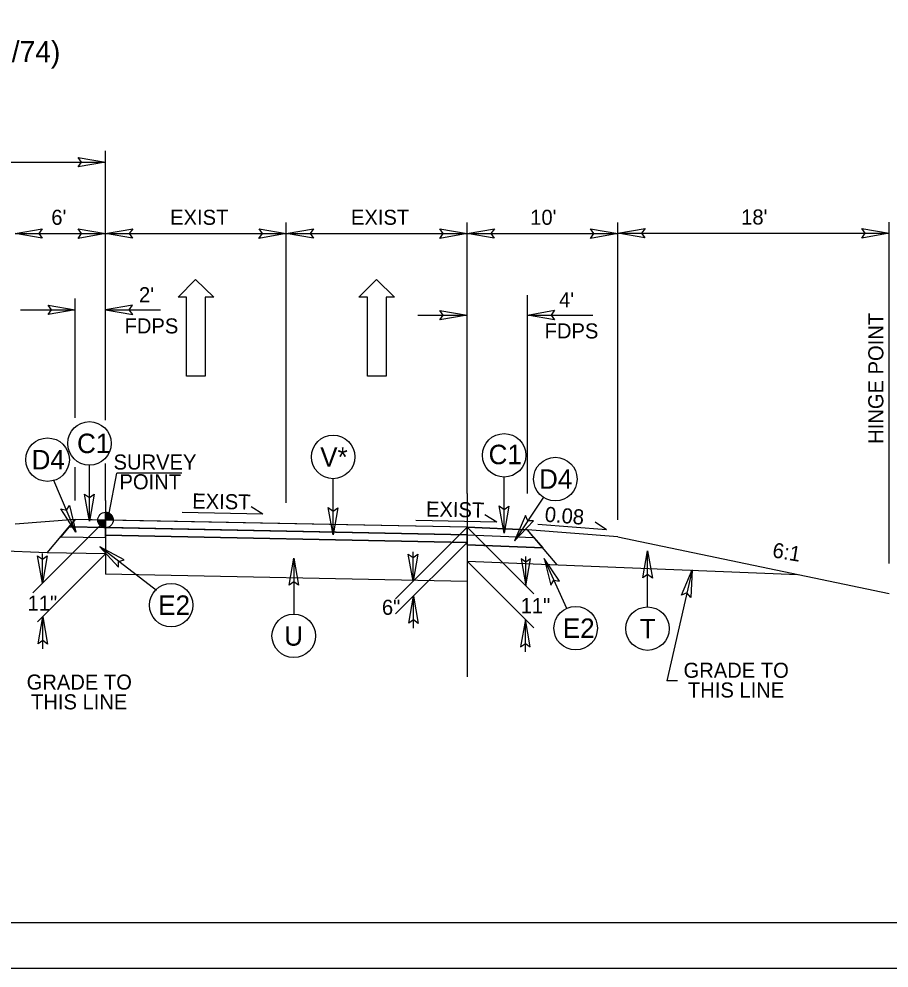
# Model space of a CAD drawing. Extents: x 18938 to 19565, y 6931 to 7973.
# Drawn here: x 19289 to 19346.7, y 7224.9 to 7287.9 of the extents above; entities that cross this region are included whole.
import ezdxf

# ---------------------------------------------------------------- set-up
doc = ezdxf.new("R2010")
doc.units = 0
for name, color, linetype in [('Old_Level_1', 7, 'Continuous'), ('Old_Level_11', 7, 'Continuous'), ('Old_Level_2', 7, 'Continuous'), ('Old_Level_3', 7, 'Continuous'), ('Prop Dimension', 7, 'Continuous'), ('Prop Pavement Schedule Description CELL', 7, 'Continuous'), ('Prop Shade Light', 7, 'Continuous'), ('Prop Terminator CELL', 7, 'Continuous'), ('Sheet Block Title CELL', 7, 'Continuous'), ('Sheet Data Field CELL', 7, 'Continuous'), ('Sheet Plot Border Inside CELL', 7, 'Continuous'), ('Sheet Plot Border Outside CELL', 7, 'Continuous'), ('Sheet Typical CELL', 7, 'Continuous'), ('Typical Bridge Rail Two Bar CELL', 7, 'Continuous'), ('Typical Detail Wedge1 CELL', 7, 'Continuous'), ('Typical Detail Wedge3 CELL', 7, 'Continuous'), ('Typical Hinge Slope Arterial CELL', 7, 'Continuous'), ('Typical ID Circle CELL', 7, 'Continuous'), ('Typical Pavement Slope Information CELL', 7, 'Continuous'), ('Typical Shoulder Slope Information CELL', 7, 'Continuous'), ('Typical Terminator CELL', 7, 'Continuous'), ('Typical Text Grade Point CELL', 7, 'Continuous'), ('Typical Text ID Circle CELL', 7, 'Continuous'), ('Typical Text Label CELL', 7, 'Continuous')]:
    doc.layers.add(name, color=color, linetype=linetype)

msp = doc.modelspace()

# ---------------------------------------------------------------- linework, layer by layer
at = {"layer": 'Old_Level_1'}
for p, q in [((19290.827, 7252.435), (19292.697, 7254.648)), ((19318.697, 7254.128), (19292.697, 7254.648)), ((19318.697, 7254.128), (19322.697, 7253.968)), ((19324.666, 7251.639), (19322.697, 7253.968)), ((19318.697, 7253.128), (19294.697, 7253.608)), ((19318.697, 7253.628), (19323.135, 7253.45)), ((19294.697, 7252.358), (19290.827, 7252.435)), ((19318.697, 7252.961), (19323.718, 7252.76)), ((19318.697, 7252.961), (19318.697, 7252.961)), ((19318.697, 7251.878), (19340.637, 7251))]:
    msp.add_line(p, q, dxfattribs=at)
at = {"layer": 'Old_Level_3'}
for p, q in [((19294.697, 7261.245), (19294.697, 7279.12)), ((19258.697, 7278.369), (19294.697, 7278.369)), ((19328.697, 7254.619), (19328.697, 7274.356)), ((19346.697, 7251.725), (19346.697, 7274.376)), ((19288.697, 7273.621), (19294.697, 7273.621)), ((19294.697, 7273.621), (19306.697, 7273.621)), ((19306.697, 7273.621), (19318.697, 7273.621)), ((19318.697, 7273.621), (19328.697, 7273.621)), ((19328.697, 7273.641), (19346.697, 7273.641)), ((19292.697, 7261.402), (19292.697, 7269.304)), ((19289.055, 7268.568), (19292.697, 7268.568)), ((19294.697, 7268.568), (19298.34, 7268.568)), ((19315.422, 7268.209), (19318.697, 7268.209)), ((19322.697, 7268.209), (19327.044, 7268.209)), ((19292.697, 7255.908), (19292.697, 7258.107)), ((19294.697, 7255.908), (19294.697, 7258.368)), ((19294.698, 7254.608), (19289.874, 7249.784)), ((19318.697, 7254.128), (19313.951, 7249.381)), ((19318.697, 7254.128), (19323.116, 7249.709)), ((19318.697, 7253.128), (19313.951, 7248.381)), ((19315.111, 7250.542), (19315.111, 7252.497)), ((19294.698, 7252.358), (19290.182, 7247.842)), ((19290.515, 7250.425), (19290.515, 7252.381)), ((19318.697, 7251.878), (19323.116, 7247.459)), ((19322.591, 7250.234), (19322.591, 7252.19)), ((19333.624, 7251.31), (19331.962, 7243.94)), ((19315.133, 7247.427), (19315.133, 7249.556)), ((19290.537, 7246.061), (19290.537, 7248.19)), ((19322.569, 7245.869), (19322.569, 7247.999)), ((19332.669, 7243.94), (19331.962, 7243.94))]:
    msp.add_line(p, q, dxfattribs=at)
at = {"layer": 'Prop Dimension'}
msp.add_lwpolyline([(19155.167, 7224.873), (19382.434, 7224.873), (19382.434, 7371.306), (19155.167, 7371.306)], close=True, dxfattribs=at)
at = {"layer": 'Prop Pavement Schedule Description CELL'}
for p, q in [((19292.697, 7254.648), (19288.697, 7254.328)), ((19328.697, 7253.488), (19322.697, 7253.968)), ((19328.697, 7253.488), (19346.698, 7249.738)), ((19290.827, 7252.435), (19280.455, 7252.869))]:
    msp.add_line(p, q, dxfattribs=at)
at = {"layer": 'Sheet Block Title CELL'}
for p, q in [((19292.282, 7254.156), (19291.728, 7253.501)), ((19294.697, 7254.108), (19292.282, 7254.156)), ((19294.697, 7253.441), (19294.697, 7254.108)), ((19318.697, 7253.628), (19294.799, 7254.106)), ((19291.728, 7253.501), (19294.697, 7253.441)), ((19318.697, 7253.628), (19323.135, 7253.45)), ((19318.697, 7252.961), (19318.697, 7253.628)), ((19323.135, 7253.45), (19323.718, 7252.76)), ((19323.718, 7252.76), (19318.697, 7252.961)), ((19318.697, 7252.961), (19318.697, 7252.961)), ((19318.697, 7252.961), (19318.697, 7252.961))]:
    msp.add_line(p, q, dxfattribs=at)
at = {"layer": 'Sheet Data Field CELL'}
for points in [[(19292.897, 7278.679), (19294.697, 7278.369), (19292.887, 7278.049), (19293.117, 7278.369)], [(19290.497, 7273.311), (19288.697, 7273.621), (19290.507, 7273.941), (19290.277, 7273.621)], [(19292.897, 7273.931), (19294.697, 7273.621), (19292.887, 7273.301), (19293.117, 7273.621)], [(19296.497, 7273.311), (19294.697, 7273.621), (19296.507, 7273.941), (19296.277, 7273.621)], [(19304.897, 7273.931), (19306.697, 7273.621), (19304.887, 7273.301), (19305.117, 7273.621)], [(19308.497, 7273.311), (19306.697, 7273.621), (19308.507, 7273.941), (19308.277, 7273.621)], [(19316.897, 7273.931), (19318.697, 7273.621), (19316.887, 7273.301), (19317.117, 7273.621)], [(19320.497, 7273.311), (19318.697, 7273.621), (19320.507, 7273.941), (19320.277, 7273.621)], [(19326.897, 7273.931), (19328.697, 7273.621), (19326.887, 7273.301), (19327.117, 7273.621)], [(19330.497, 7273.331), (19328.697, 7273.641), (19330.507, 7273.961), (19330.277, 7273.641)], [(19344.897, 7273.951), (19346.697, 7273.641), (19344.887, 7273.321), (19345.117, 7273.641)], [(19290.897, 7268.878), (19292.697, 7268.568), (19290.887, 7268.248), (19291.117, 7268.568)], [(19296.497, 7268.878), (19294.697, 7268.568), (19296.507, 7268.248), (19296.277, 7268.568)], [(19316.897, 7268.519), (19318.697, 7268.209), (19316.887, 7267.889), (19317.117, 7268.209)], [(19324.497, 7267.899), (19322.697, 7268.209), (19324.507, 7268.529), (19324.277, 7268.209)], [(19293.946, 7256.326), (19293.636, 7254.526), (19293.316, 7256.336), (19293.636, 7256.106)], [(19292.315, 7255.578), (19292.727, 7253.798), (19291.73, 7255.343), (19292.114, 7255.255)], [(19310.117, 7255.425), (19309.807, 7253.625), (19309.487, 7255.435), (19309.807, 7255.205)], [(19321.466, 7255.535), (19321.156, 7253.735), (19320.836, 7255.545), (19321.156, 7255.315)], [(19322.582, 7254.901), (19321.85, 7253.228), (19323.113, 7254.562), (19322.72, 7254.547)], [(19295.931, 7251.973), (19294.317, 7252.829), (19295.553, 7251.469), (19295.567, 7251.863)], [(19330.361, 7250.77), (19330.671, 7252.57), (19330.991, 7250.76), (19330.671, 7250.99)], [(19290.825, 7252.225), (19290.515, 7250.425), (19290.195, 7252.235), (19290.515, 7252.005)], [(19306.881, 7250.286), (19307.191, 7252.086), (19307.511, 7250.276), (19307.191, 7250.506)], [(19315.421, 7252.342), (19315.111, 7250.542), (19314.791, 7252.352), (19315.111, 7252.122)], [(19322.281, 7252.034), (19322.591, 7250.234), (19322.911, 7252.044), (19322.591, 7251.814)], [(19324.834, 7250.553), (19323.811, 7252.066), (19324.263, 7250.285), (19324.46, 7250.626)], [(19332.925, 7249.623), (19333.624, 7251.31), (19333.538, 7249.474), (19333.276, 7249.769)], [(19314.823, 7247.756), (19315.133, 7249.556), (19315.453, 7247.746), (19315.133, 7247.976)], [(19290.227, 7246.39), (19290.537, 7248.19), (19290.857, 7246.38), (19290.537, 7246.61)], [(19322.879, 7246.199), (19322.569, 7247.999), (19322.249, 7246.189), (19322.569, 7246.419)]]:
    msp.add_lwpolyline(points, close=True, dxfattribs=at)
at = {"layer": 'Sheet Typical CELL'}
for p, q in [((19306.697, 7255.743), (19306.697, 7274.356)), ((19318.697, 7256.372), (19318.697, 7274.356)), ((19322.697, 7256.372), (19322.697, 7269.543))]:
    msp.add_line(p, q, dxfattribs=at)
at = {"layer": 'Typical Bridge Rail Two Bar CELL'}
for p, q in [((19318.697, 7256.372), (19318.697, 7244.193)), ((19294.697, 7255.908), (19294.697, 7251.019))]:
    msp.add_line(p, q, dxfattribs=at)
at = {"layer": 'Typical Detail Wedge1 CELL'}
for p, q in [((19294.698, 7254.608), (19294.698, 7255.12)), ((19294.186, 7254.608), (19294.698, 7254.608)), ((19294.697, 7254.096), (19294.698, 7254.608)), ((19294.698, 7254.608), (19294.697, 7254.096)), ((19295.21, 7254.608), (19294.698, 7254.608))]:
    msp.add_line(p, q, dxfattribs=at)
for points in [[(19294.703, 7255.12), (19294.703, 7255.12), (19294.703, 7254.608)], [(19294.713, 7255.119), (19294.713, 7254.608)], [(19294.723, 7255.119), (19294.723, 7254.608)], [(19294.734, 7255.119), (19294.733, 7254.608)], [(19294.744, 7255.117), (19294.744, 7254.608)], [(19294.754, 7255.117), (19294.754, 7254.608)], [(19294.764, 7255.116), (19294.764, 7254.608)], [(19294.774, 7255.114), (19294.774, 7254.608)], [(19294.785, 7255.112), (19294.784, 7254.608)], [(19294.795, 7255.11), (19294.795, 7254.608)], [(19294.805, 7255.108), (19294.805, 7254.608)], [(19294.815, 7255.106), (19294.815, 7254.608)], [(19294.826, 7255.104), (19294.826, 7254.608)], [(19294.836, 7255.101), (19294.836, 7254.608)], [(19294.846, 7255.098), (19294.846, 7254.608)], [(19294.857, 7255.095), (19294.857, 7254.608)], [(19294.867, 7255.091), (19294.867, 7254.608)], [(19294.877, 7255.087), (19294.877, 7254.608)], [(19294.887, 7255.084), (19294.887, 7254.608)], [(19294.898, 7255.079), (19294.897, 7254.608)], [(19294.908, 7255.075), (19294.908, 7254.608)], [(19294.918, 7255.07), (19294.918, 7254.608)], [(19294.928, 7255.065), (19294.928, 7254.608)], [(19294.938, 7255.06), (19294.938, 7254.608)], [(19294.949, 7255.054), (19294.948, 7254.608)], [(19294.959, 7255.048), (19294.959, 7254.608)], [(19294.969, 7255.042), (19294.969, 7254.608)], [(19294.979, 7255.035), (19294.979, 7254.608)], [(19294.989, 7255.029), (19294.989, 7254.608)], [(19295, 7255.021), (19295, 7254.608)], [(19295.01, 7255.013), (19295.01, 7254.608)], [(19295.02, 7255.005), (19295.02, 7254.608)], [(19295.03, 7254.997), (19295.03, 7254.608)], [(19295.041, 7254.988), (19295.041, 7254.608)], [(19295.051, 7254.978), (19295.051, 7254.608)], [(19295.061, 7254.968), (19295.061, 7254.608)], [(19295.072, 7254.958), (19295.072, 7254.608)], [(19295.082, 7254.946), (19295.082, 7254.608)], [(19294.189, 7254.608), (19294.189, 7254.552)], [(19294.199, 7254.608), (19294.199, 7254.492)], [(19294.209, 7254.608), (19294.209, 7254.454)], [(19294.22, 7254.608), (19294.22, 7254.425)], [(19294.23, 7254.608), (19294.23, 7254.4)], [(19294.24, 7254.608), (19294.24, 7254.378)], [(19294.25, 7254.608), (19294.25, 7254.359)], [(19294.26, 7254.608), (19294.26, 7254.342)], [(19294.271, 7254.608), (19294.271, 7254.326)], [(19294.281, 7254.608), (19294.281, 7254.31)], [(19294.291, 7254.608), (19294.291, 7254.297)], [(19294.301, 7254.608), (19294.301, 7254.284)], [(19294.311, 7254.608), (19294.311, 7254.272)], [(19294.322, 7254.608), (19294.322, 7254.26)], [(19294.332, 7254.608), (19294.332, 7254.249)], [(19294.342, 7254.608), (19294.342, 7254.239)], [(19294.353, 7254.608), (19294.353, 7254.23)], [(19294.363, 7254.608), (19294.363, 7254.221)], [(19294.373, 7254.608), (19294.373, 7254.212)], [(19294.383, 7254.608), (19294.383, 7254.204)], [(19294.394, 7254.608), (19294.394, 7254.196)], [(19294.404, 7254.608), (19294.404, 7254.189)], [(19294.414, 7254.608), (19294.414, 7254.181)], [(19294.424, 7254.608), (19294.424, 7254.175)], [(19294.435, 7254.608), (19294.434, 7254.168)], [(19294.445, 7254.608), (19294.445, 7254.162)], [(19294.455, 7254.608), (19294.455, 7254.157)], [(19294.465, 7254.608), (19294.465, 7254.152)], [(19294.475, 7254.608), (19294.475, 7254.146)], [(19294.486, 7254.608), (19294.485, 7254.142)], [(19294.496, 7254.608), (19294.496, 7254.137)], [(19294.506, 7254.608), (19294.506, 7254.133)], [(19294.516, 7254.608), (19294.516, 7254.129)], [(19294.527, 7254.608), (19294.527, 7254.125)], [(19294.537, 7254.608), (19294.537, 7254.121)], [(19294.547, 7254.608), (19294.547, 7254.118)], [(19294.557, 7254.608), (19294.557, 7254.115)], [(19294.568, 7254.608), (19294.568, 7254.112)], [(19294.578, 7254.608), (19294.578, 7254.11)], [(19294.588, 7254.608), (19294.588, 7254.108)], [(19294.599, 7254.608), (19294.598, 7254.105)], [(19294.609, 7254.608), (19294.609, 7254.104)], [(19294.619, 7254.608), (19294.619, 7254.102)], [(19294.629, 7254.608), (19294.629, 7254.1)], [(19294.639, 7254.608), (19294.639, 7254.099)], [(19294.65, 7254.608), (19294.649, 7254.098)], [(19294.66, 7254.608), (19294.66, 7254.097)], [(19294.67, 7254.608), (19294.67, 7254.097)], [(19294.68, 7254.608), (19294.68, 7254.096)], [(19294.69, 7254.608), (19294.69, 7254.096), (19294.69, 7254.096)], [(19295.092, 7254.934), (19295.092, 7254.608)], [(19295.102, 7254.921), (19295.102, 7254.608)], [(19295.113, 7254.908), (19295.112, 7254.608)], [(19295.123, 7254.893), (19295.123, 7254.608)], [(19295.133, 7254.877), (19295.133, 7254.608)], [(19295.143, 7254.86), (19295.143, 7254.608)], [(19295.153, 7254.842), (19295.153, 7254.608)], [(19295.164, 7254.82), (19295.163, 7254.608)], [(19295.174, 7254.796), (19295.174, 7254.608)], [(19295.184, 7254.768), (19295.184, 7254.608)], [(19295.194, 7254.732), (19295.194, 7254.608)], [(19295.204, 7254.68), (19295.204, 7254.608)]]:
    msp.add_lwpolyline(points, dxfattribs=at)
msp.add_circle((19294.698, 7254.608), 0.512, dxfattribs=at)
for start, end in [(359.99048, 89.99048), (179.99048, 269.99048)]:
    msp.add_arc((19294.698, 7254.608), 0.512, start, end, dxfattribs=at)
at = {"layer": 'Typical Detail Wedge3 CELL'}
for p, q in [((19299.517, 7269.399), (19300.68, 7270.58)), ((19300.68, 7270.58), (19301.88, 7269.399)), ((19311.517, 7269.399), (19312.68, 7270.58)), ((19312.68, 7270.58), (19313.88, 7269.399)), ((19300.08, 7269.399), (19299.517, 7269.399)), ((19300.08, 7264.149), (19300.08, 7269.399)), ((19301.88, 7269.399), (19301.317, 7269.399)), ((19301.317, 7269.399), (19301.317, 7264.149)), ((19312.08, 7269.399), (19311.517, 7269.399)), ((19312.08, 7264.149), (19312.08, 7269.399)), ((19313.88, 7269.399), (19313.317, 7269.399)), ((19313.317, 7269.399), (19313.317, 7264.149)), ((19301.317, 7264.149), (19300.08, 7264.149)), ((19313.317, 7264.149), (19312.08, 7264.149))]:
    msp.add_line(p, q, dxfattribs=at)
at = {"layer": 'Typical Hinge Slope Arterial CELL'}
for p, q in [((19292.697, 7254.648), (19292.282, 7254.156)), ((19294.697, 7254.608), (19292.697, 7254.648)), ((19294.697, 7254.108), (19294.697, 7254.608)), ((19292.282, 7254.156), (19294.697, 7254.108)), ((19322.697, 7253.968), (19318.697, 7254.128)), ((19318.697, 7254.128), (19318.697, 7253.628)), ((19323.135, 7253.45), (19322.697, 7253.968)), ((19318.697, 7253.628), (19323.135, 7253.45))]:
    msp.add_line(p, q, dxfattribs=at)
msp.add_lwpolyline([(19294.698, 7254.608), (19294.697, 7254.108), (19318.697, 7253.628), (19318.697, 7254.128)], close=True, dxfattribs=at)
at = {"layer": 'Typical ID Circle CELL'}
for p, q in [((19318.697, 7253.128), (19294.697, 7253.608)), ((19294.697, 7253.608), (19318.697, 7253.128)), ((19294.697, 7253.441), (19294.697, 7251.019)), ((19318.697, 7253.321), (19318.697, 7250.539)), ((19318.697, 7250.539), (19294.697, 7251.019))]:
    msp.add_line(p, q, dxfattribs=at)
at = {"layer": 'Typical Pavement Slope Information CELL'}
msp.add_lwpolyline([(19380.142, 7368.299), (19177.642, 7368.299), (19177.642, 7227.884), (19380.142, 7227.884)], close=True, dxfattribs=at)
at = {"layer": 'Typical Terminator CELL'}
for p, q in [((19293.636, 7254.526), (19293.636, 7258.254)), ((19321.156, 7253.735), (19321.156, 7257.463)), ((19292.727, 7253.798), (19291.282, 7257.235)), ((19309.807, 7253.625), (19309.807, 7257.353)), ((19323.76, 7256.125), (19321.85, 7253.228)), ((19298.076, 7249.923), (19294.317, 7252.829)), ((19330.671, 7248.842), (19330.671, 7252.57)), ((19307.191, 7252.086), (19307.191, 7248.358)), ((19325.309, 7248.743), (19323.811, 7252.066))]:
    msp.add_line(p, q, dxfattribs=at)
for centre in [(19293.636, 7259.697), (19290.858, 7258.614), (19309.807, 7258.796), (19321.156, 7258.905), (19324.555, 7257.329), (19299.053, 7248.958), (19325.902, 7247.428), (19330.67, 7247.4), (19307.191, 7246.916)]:
    msp.add_circle(centre, 1.443, dxfattribs=at)
at = {"layer": 'Typical Text Grade Point CELL'}
for p, q in [((19305.15, 7255.008), (19299.794, 7255.115)), ((19305.15, 7255.008), (19304.367, 7255.481)), ((19320.66, 7254.475), (19319.877, 7254.949)), ((19320.66, 7254.475), (19315.304, 7254.583)), ((19327.95, 7253.952), (19323.391, 7254.317)), ((19327.95, 7253.952), (19327.193, 7254.465))]:
    msp.add_line(p, q, dxfattribs=at)
at = {"layer": 'Typical Text ID Circle CELL'}
for p in [(19294.948, 7255.061), (19299.758, 7257.728)]:
    msp.add_line(p, (19295.443, 7257.729), dxfattribs=at)

# ---------------------------------------------------------------- texts
at = {"layer": 'Old_Level_11'}
for s, p in [('GRADE TO', (19333.063, 7244.137)), ('GRADE TO', (19289.467, 7243.353)), ('THIS LINE', (19333.354, 7242.826)), ('THIS LINE', (19289.758, 7242.042))]:
    msp.add_text(s, height=1, dxfattribs=at).set_placement(p)
at = {"layer": 'Old_Level_2'}
for s, rotation, p in [('11"', 0, (19289.53, 7248.587)), ('6"', 0, (19313.046, 7248.317)), ('11"', 360, (19322.252, 7248.426))]:
    msp.add_text(s, height=1, rotation=rotation, dxfattribs=at).set_placement(p)
at = {"layer": 'Old_Level_3'}
for s, p in [("6'", (19291.104, 7274.203)), ('EXIST', (19298.99, 7274.203)), ('EXIST', (19310.99, 7274.203)), ("10'", (19322.887, 7274.203)), ("18'", (19336.887, 7274.223)), ("2'", (19296.925, 7269.065)), ("4'", (19324.801, 7268.733)), ('FDPS', (19295.967, 7266.994)), ('FDPS', (19323.843, 7266.661))]:
    msp.add_text(s, height=1, dxfattribs=at).set_placement(p)
at = {"layer": 'Prop Shade Light'}
msp.add_text('HINGE POINT', height=1, rotation=90, dxfattribs=at).set_placement((19346.322, 7259.666))
at = {"layer": 'Prop Terminator CELL'}
for s, height, p in [('C1', 1.2912, (19292.813, 7259.051)), ('V*', 1.2912, (19308.951, 7258.15)), ('C1', 1.2912, (19320.125, 7258.315)), ('D4', 1.2912, (19289.797, 7257.968)), ('D4', 1.2912, (19323.473, 7256.683)), ('E2', 1.2912, (19298.202, 7248.313)), ('E2', 1.2912, (19325.051, 7246.783)), ('T', 1.291, (19330.162, 7246.754)), ('U', 1.291, (19306.559, 7246.27))]:
    msp.add_text(s, height=height, dxfattribs=at).set_placement(p)
at = {"layer": 'Sheet Plot Border Inside CELL'}
msp.add_text('0.08', height=1, rotation=355.29343, dxfattribs=at).set_placement((19323.823, 7254.506))
at = {"layer": 'Sheet Plot Border Outside CELL'}
for s, p in [('SURVEY', (19295.235, 7257.959)), ('POINT', (19295.628, 7256.648))]:
    msp.add_text(s, height=1, rotation=0.00004, dxfattribs=at).set_placement(p)
at = {"layer": 'Typical Shoulder Slope Information CELL'}
msp.add_text('6:1', height=1, rotation=350.53741, dxfattribs=at).set_placement((19338.912, 7252.141))
at = {"layer": 'Typical Text Grade Point CELL'}
for p in [(19300.451, 7255.377), (19315.961, 7254.845)]:
    msp.add_text('EXIST', height=1, rotation=358.85426, dxfattribs=at).set_placement(p)
at = {"layer": 'Typical Text Label CELL'}
msp.add_text('C -Y12- (US 64/74)', height=1.4, rotation=359.9469, dxfattribs=at).set_placement((19275.681, 7285.013))

doc.saveas('drawing.dxf')
